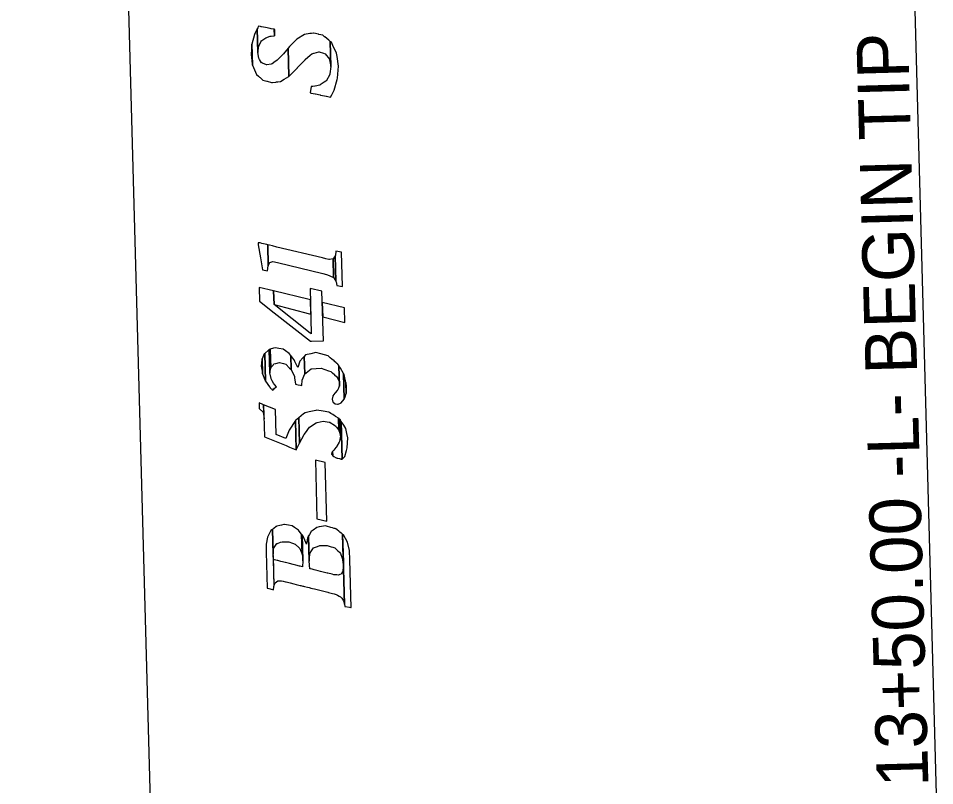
# Model space of a CAD drawing. Extents: x 1835096 to 1837089, y 993071 to 995976.
# Drawn here: x 1835140.8 to 1835495.4, y 994065.2 to 994362.2 of the extents above; entities that cross this region are included whole.
import ezdxf

# ---------------------------------------------------------------- set-up
doc = ezdxf.new("R2010")
doc.units = 0
for name, color, linetype in [('CTL Sheet Border CELL', 7, 'Continuous'), ('Default', 7, 'Continuous'), ('Sheet Data Field CELL', 7, 'Continuous')]:
    doc.layers.add(name, color=color, linetype=linetype)

msp = doc.modelspace()

# ---------------------------------------------------------------- linework, layer by layer
at = {"layer": 'CTL Sheet Border CELL'}
msp.add_lwpolyline([(1835140.76, 995926.46), (1835211.98, 993318.73), (1837037.37, 993368.58), (1836966.16, 995976.31)], close=True, dxfattribs=at)
at = {"layer": 'Default'}
msp.add_line((1835497.85, 993999.18), (1835481.16, 994610.43), dxfattribs=at)
at = {"layer": 'Sheet Data Field CELL'}
for points in [[(1835238.65, 994355.27), (1835239.88, 994355.41), (1835239.81, 994357.91), (1835238.57, 994358.15), (1835238.26, 994358.21), (1835238.2, 994358.22), (1835236.47, 994358.56), (1835236.47, 994358.55), (1835236.4, 994358.57), (1835234.85, 994358.86), (1835234.68, 994358.9), (1835234.68, 994358.9), (1835234.47, 994358.94), (1835233.75, 994359.08), (1835233.6, 994358.79), (1835233.47, 994358.54), (1835233.22, 994358.05), (1835233.47, 994348.99), (1835233.69, 994350.55), (1835233.8, 994351.37), (1835233.95, 994351.66), (1835234.63, 994353.01), (1835234.83, 994353.41), (1835235, 994353.53), (1835236.51, 994354.64), (1835236.58, 994354.67), (1835238.28, 994355.23), (1835238.34, 994355.23)], [(1835243.59, 994338.57), (1835245.48, 994339.66), (1835245.18, 994350.6), (1835243.32, 994348.46), (1835241.9, 994347), (1835241.9, 994346.99), (1835240.95, 994346.01), (1835240.39, 994345.59), (1835240.15, 994345.41), (1835238.95, 994344.5), (1835238.63, 994344.44), (1835238.58, 994344.43), (1835236.87, 994344.1), (1835236.79, 994344.13), (1835235.24, 994344.82), (1835235.07, 994344.9), (1835235.07, 994344.89), (1835234.85, 994344.99), (1835234.1, 994346.25), (1835233.94, 994346.52), (1835233.79, 994346.77), (1835233.47, 994348.99), (1835233.22, 994358.05), (1835232.46, 994356.57), (1835232.14, 994355.95), (1835231.12, 994352.15), (1835231.35, 994344.02), (1835232.54, 994341.28), (1835232.9, 994340.46), (1835233.72, 994339.73), (1835233.99, 994339.49), (1835234.13, 994339.36), (1835234.29, 994339.22), (1835235.03, 994338.57), (1835235.24, 994338.38), (1835235.42, 994338.23), (1835236.97, 994337.8), (1835237.04, 994337.78), (1835238.77, 994337.3), (1835238.83, 994337.29), (1835239.14, 994337.33), (1835240.37, 994337.5), (1835240.61, 994337.53), (1835241.18, 994337.61), (1835242.16, 994337.75)], [(1835239.88, 994355.41), (1835240.06, 994357.86), (1835239.81, 994357.91)], [(1835261.21, 994346.14), (1835261.74, 994343.51), (1835261.47, 994353.25), (1835261.01, 994353.64), (1835260.96, 994353.67), (1835260.95, 994353.68), (1835259.36, 994355), (1835259.3, 994355.05), (1835258.66, 994355.59), (1835257.05, 994355.96), (1835256.88, 994356.01), (1835255.07, 994356.44), (1835254.95, 994356.47), (1835254.16, 994356.33), (1835253.51, 994356.23), (1835251.52, 994355.89), (1835251.46, 994355.89), (1835248.54, 994354.09), (1835248.51, 994354.08), (1835245.7, 994351.2), (1835245.18, 994350.6), (1835245.48, 994339.66), (1835246, 994340.19), (1835248.81, 994343.04), (1835248.84, 994343.08), (1835251.72, 994346.11), (1835251.79, 994346.17), (1835253.74, 994347.89), (1835254.38, 994348.45), (1835255.17, 994348.67), (1835255.28, 994348.7), (1835257.07, 994349.22), (1835257.24, 994349.16), (1835258.84, 994348.67), (1835259.48, 994348.48), (1835259.54, 994348.46), (1835261.15, 994346.4), (1835261.16, 994346.39)], [(1835231.28, 994344.61), (1835231.35, 994344.02), (1835231.12, 994352.15), (1835231.08, 994351.98), (1835230.87, 994348.12)], [(1835264.34, 994338.99), (1835264.64, 994343.68), (1835264.11, 994347.4), (1835263.93, 994348.68), (1835262.48, 994351.69), (1835261.91, 994352.89), (1835261.47, 994353.25), (1835261.74, 994343.51), (1835261.36, 994340.7), (1835261.33, 994340.44), (1835261.32, 994340.38), (1835259.83, 994337.88), (1835259.77, 994337.8), (1835259.15, 994337.39), (1835257.59, 994336.36), (1835257.42, 994336.32), (1835255.63, 994335.88), (1835255.51, 994335.87), (1835254.73, 994335.82), (1835254.07, 994335.78), (1835253.68, 994333.29), (1835254.14, 994333.19), (1835254.8, 994333.06), (1835255.6, 994332.9), (1835255.71, 994332.88), (1835257.53, 994332.52), (1835257.69, 994332.48), (1835259.3, 994332.16), (1835259.93, 994332.03), (1835259.99, 994332.02), (1835261.55, 994331.71), (1835261.56, 994331.7), (1835261.61, 994331.7), (1835262.04, 994332.52), (1835262.45, 994333.32), (1835262.96, 994334.3), (1835264.2, 994338.52)], [(1835237.21, 994264.43), (1835237.5, 994266.44), (1835237.28, 994274.54), (1835236.93, 994274.63), (1835235.01, 994275.09), (1835234.32, 994275.26), (1835233.6, 994275.23), (1835233.61, 994274.54), (1835233.63, 994274.46), (1835234.48, 994269.51), (1835235.29, 994264.78)], [(1835261.37, 994262.55), (1835262.76, 994261.85), (1835262.56, 994269.07), (1835261.19, 994268.84), (1835260.92, 994268.88), (1835259.81, 994269.08), (1835258.42, 994269.42), (1835240.86, 994273.67), (1835239.11, 994274.1), (1835237.94, 994274.38), (1835237.28, 994274.54), (1835237.5, 994266.43), (1835238.12, 994267.73), (1835239.27, 994268.02), (1835241.02, 994267.73), (1835258.58, 994263.45), (1835259.97, 994263.03), (1835261.09, 994262.7)], [(1835264.03, 994258.77), (1835266.18, 994258.4), (1835265.82, 994271.62), (1835263.67, 994272.08), (1835263.45, 994270.37), (1835263.39, 994270.27), (1835263.66, 994260.46), (1835263.73, 994260.14)], [(1835262.85, 994261.69), (1835263.66, 994260.47), (1835263.39, 994270.27), (1835262.65, 994269.09), (1835262.56, 994269.07), (1835262.76, 994261.84)], [(1835254.21, 994237.23), (1835258.8, 994237.36), (1835258.27, 994256.56), (1835253.65, 994257.65), (1835254.14, 994240.05), (1835253.7, 994240.38), (1835239.71, 994251.36), (1835239.56, 994256.66), (1835233.93, 994258.01), (1835234.07, 994252.69), (1835239.79, 994248.2), (1835253.79, 994237.22)], [(1835253.5, 994247.87), (1835253.92, 994247.77), (1835253.77, 994253.27), (1835253.35, 994253.37), (1835239.56, 994256.66), (1835239.71, 994251.36)], [(1835258.54, 994246.63), (1835267.09, 994244.5), (1835266.93, 994250.13), (1835258.39, 994252.17)], [(1835236.21, 994222.26), (1835236.4, 994221.8), (1835236.11, 994232.49), (1835235.94, 994232.33), (1835235.1, 994230.35), (1835235.26, 994224.58)], [(1835239.96, 994219), (1835240.63, 994219.55), (1835239.92, 994220.46), (1835239.54, 994220.95), (1835238.99, 994221.94), (1835238.59, 994222.67), (1835238.55, 994222.75), (1835238.12, 994224.93), (1835237.87, 994234.04), (1835237.81, 994234.02), (1835237.55, 994233.79), (1835236.11, 994232.49), (1835236.4, 994221.79), (1835237.94, 994219.6), (1835238.21, 994219.29), (1835238.28, 994219.22), (1835238.66, 994218.79), (1835238.7, 994218.74), (1835239.09, 994218.31), (1835239.6, 994218.71)], [(1835238.44, 994226.74), (1835238.48, 994226.96), (1835238.28, 994234.14), (1835238.24, 994234.14), (1835237.87, 994234.04), (1835238.12, 994224.93)], [(1835245.72, 994226.84), (1835246.33, 994226.24), (1835246.18, 994231.72), (1835245.57, 994232.51), (1835244.14, 994233.47), (1835243.22, 994234.1), (1835241.63, 994234.41), (1835240.28, 994234.67), (1835240.22, 994234.65), (1835239.54, 994234.48), (1835239.54, 994234.47), (1835239.17, 994234.38), (1835238.66, 994234.24), (1835238.28, 994234.15), (1835238.48, 994226.95), (1835238.84, 994227.39), (1835239.34, 994227.99), (1835239.7, 994228.41), (1835240.38, 994228.6), (1835240.44, 994228.62), (1835241.77, 994228.99), (1835243.37, 994228.54), (1835244.28, 994228.29)], [(1835250.62, 994222.19), (1835251.58, 994224.64), (1835251.4, 994231.35), (1835250.4, 994230.24), (1835250.2, 994230.03), (1835249.68, 994229.46), (1835248.91, 994227.01), (1835247.79, 994229.37), (1835247.48, 994230.04), (1835247.43, 994230.11), (1835246.18, 994231.72), (1835246.33, 994226.24), (1835247.61, 994223.56), (1835247.67, 994223.11), (1835248.03, 994220.58), (1835249.09, 994220.37), (1835249.93, 994220.21), (1835250.47, 994220.1)], [(1835264.9, 994221.7), (1835264.99, 994219.85), (1835264.77, 994227.74), (1835264.73, 994227.82), (1835264.38, 994228.4), (1835264.11, 994228.63), (1835264.07, 994228.65), (1835263.79, 994228.89), (1835263.02, 994229.54), (1835262.94, 994229.6), (1835262.13, 994230.28), (1835262.08, 994230.33), (1835261.5, 994230.81), (1835260.66, 994231.52), (1835257.83, 994232.29), (1835255.88, 994232.82), (1835253.92, 994232.39), (1835251.94, 994231.95), (1835251.4, 994231.35), (1835251.58, 994224.63), (1835252.13, 994225.04), (1835254.08, 994226.48), (1835256.05, 994226.61), (1835257.98, 994226.74), (1835260.82, 994225.79), (1835261.65, 994225.52), (1835262.22, 994225.04), (1835262.28, 994225), (1835263.08, 994224.32), (1835263.16, 994224.25), (1835263.94, 994223.6), (1835264.23, 994223.03), (1835264.26, 994222.96), (1835264.54, 994222.41)], [(1835235.09, 994225.65), (1835235.26, 994224.58), (1835235.1, 994230.35), (1835234.97, 994230.02), (1835234.78, 994227.5)], [(1835265.75, 994213.33), (1835266.9, 994214.78), (1835266.63, 994224.68), (1835265.38, 994226.74), (1835264.77, 994227.74), (1835264.99, 994219.85), (1835264.95, 994219.76), (1835264.63, 994219.03), (1835264.38, 994218.47), (1835264.35, 994218.43), (1835264.09, 994218.11), (1835263.35, 994217.24), (1835263.28, 994217.14), (1835262.52, 994216.14), (1835262.47, 994215.95), (1835262.18, 994214.82), (1835262.18, 994214.82), (1835262.53, 994213.68), (1835262.59, 994213.64), (1835263.39, 994212.98), (1835263.47, 994212.97), (1835264.23, 994212.88), (1835264.51, 994212.84), (1835264.54, 994212.86), (1835264.8, 994212.96), (1835265.13, 994213.09), (1835265.17, 994213.11)], [(1835267.06, 994215.29), (1835267.62, 994217), (1835267.5, 994221.21), (1835266.82, 994224.38), (1835266.63, 994224.68), (1835266.9, 994214.78)], [(1835267.62, 994216.99), (1835267.72, 994220.22), (1835267.5, 994221.21)], [(1835235.5, 994209.79), (1835235.84, 994207.17), (1835235.69, 994212.62), (1835235.42, 994212.73), (1835233.96, 994213.32), (1835234.01, 994211.24)], [(1835248.27, 994195.23), (1835248.28, 994195.23), (1835247.97, 994206.55), (1835247.96, 994206.55), (1835245.56, 994202.77), (1835244.29, 994199.53), (1835240.52, 994201.11), (1835240.26, 994210.8), (1835235.69, 994212.62), (1835236.03, 994200.22), (1835240.6, 994198.36), (1835244.36, 994196.83), (1835245.74, 994196.27)], [(1835263.86, 994203.97), (1835264.8, 994202.74), (1835264.67, 994207.39), (1835263.75, 994207.99), (1835263.52, 994208.14), (1835263.33, 994208.25), (1835262.43, 994208.83), (1835262, 994209.11), (1835261.72, 994209.29), (1835261.2, 994209.63), (1835260.97, 994209.77), (1835258.67, 994210.15), (1835256.33, 994210.54), (1835255.87, 994210.43), (1835253.25, 994209.85), (1835251.71, 994209.51), (1835251.18, 994209.09), (1835249.33, 994207.62), (1835249.6, 994197.76), (1835251.4, 994201.11), (1835251.92, 994201.82), (1835253.41, 994203.9), (1835256, 994205.69), (1835256.46, 994205.78), (1835258.78, 994206.24), (1835261.08, 994205.88), (1835261.3, 994205.85), (1835261.83, 994205.52), (1835262.11, 994205.35), (1835262.53, 994205.08), (1835263.44, 994204.53), (1835263.62, 994204.28)], [(1835248.28, 994195.23), (1835249.6, 994197.77), (1835249.33, 994207.62), (1835247.97, 994206.55)], [(1835265.66, 994191.64), (1835266.13, 994191.52), (1835265.73, 994206.17), (1835265.25, 994206.91), (1835265.42, 994200.65), (1835265.31, 994199.89), (1835265.11, 994198.44), (1835264.93, 994198.11), (1835264.06, 994196.55), (1835263.84, 994196.28), (1835263.84, 994196.27), (1835263.67, 994196.07), (1835262.81, 994195.04), (1835262.4, 994194.51), (1835262.45, 994192.87), (1835262.87, 994192.64), (1835263.77, 994192.15), (1835263.96, 994192.04), (1835264.19, 994191.99), (1835265.1, 994191.78), (1835265.29, 994191.73), (1835265.54, 994191.67)], [(1835265.28, 994201.12), (1835265.42, 994200.65), (1835265.25, 994206.91), (1835265.11, 994207.11), (1835264.87, 994207.27), (1835264.67, 994207.39), (1835264.8, 994202.73), (1835265.01, 994202.03)], [(1835268.08, 994196.02), (1835268.29, 994199.87), (1835267.92, 994201.57), (1835267.52, 994203.45), (1835266.72, 994204.67), (1835265.73, 994206.17), (1835266.13, 994191.53), (1835267.05, 994192.66), (1835267.76, 994194.97)], [(1835262.16, 994193.25), (1835262.45, 994192.88), (1835262.4, 994194.51), (1835262.14, 994194.17), (1835261.99, 994193.48), (1835261.99, 994193.47)], [(1835256.33, 994168.46), (1835260.11, 994167.56), (1835259.49, 994190.31), (1835255.71, 994191.21)], [(1835239.69, 994142.38), (1835239.75, 994142.54), (1835239.47, 994152.76), (1835239.36, 994154.35), (1835239.33, 994154.88), (1835239.07, 994164.39), (1835238.91, 994164.28), (1835238.47, 994163.95), (1835237.15, 994161.42), (1835236.7, 994158.69), (1835236.73, 994155.55), (1835237.1, 994141.68), (1835237.17, 994141.66), (1835237.69, 994141.53), (1835239.09, 994141.16), (1835239.55, 994141.05), (1835239.67, 994142.22)], [(1835249.65, 994157.02), (1835250.58, 994154.8), (1835250.37, 994162.57), (1835249.47, 994163.71), (1835249.21, 994164.05), (1835247.69, 994165.09), (1835246.72, 994165.76), (1835245.32, 994166.03), (1835243.74, 994166.33), (1835243.57, 994166.29), (1835242.66, 994166.09), (1835241.99, 994165.94), (1835240.85, 994165.7), (1835240.61, 994165.52), (1835240.6, 994165.51), (1835239.62, 994164.79), (1835239.36, 994164.61), (1835239.36, 994164.6), (1835239.15, 994164.45), (1835239.09, 994164.41), (1835239.09, 994164.4), (1835239.07, 994164.39), (1835239.33, 994154.87), (1835239.34, 994155.03), (1835239.39, 994155.5), (1835239.56, 994157.07), (1835239.82, 994157.44), (1835240.78, 994158.89), (1835240.79, 994158.89), (1835241.03, 994158.98), (1835242.17, 994159.4), (1835242.83, 994159.65), (1835243.75, 994159.62), (1835243.92, 994159.62), (1835245.49, 994159.59), (1835246.9, 994159.06), (1835247.87, 994158.69), (1835249.39, 994157.26)], [(1835266.25, 994152.51), (1835266.55, 994151.55), (1835266.25, 994162.55), (1835265.97, 994162.77), (1835265.75, 994162.94), (1835265.75, 994162.94), (1835265.2, 994163.37), (1835265.19, 994163.38), (1835264.78, 994163.7), (1835264.18, 994164.17), (1835263.59, 994164.64), (1835263.37, 994164.7), (1835263.02, 994164.8), (1835262.32, 994165), (1835261.67, 994165.18), (1835260.04, 994165.65), (1835259.78, 994165.73), (1835257.24, 994165.34), (1835256.31, 994165.2), (1835254.81, 994164.12), (1835254.03, 994163.56), (1835253.43, 994162.47), (1835253.2, 994162.04), (1835253.1, 994161.86), (1835253.36, 994152.14), (1835253.44, 994153.03), (1835253.63, 994155.1), (1835254.24, 994156.05), (1835254.99, 994157.23), (1835256.51, 994157.79), (1835257.44, 994158.15), (1835259.99, 994158.17), (1835260.24, 994158.18), (1835261.88, 994157.69), (1835262.53, 994157.49), (1835263.23, 994157.28), (1835263.59, 994156.93), (1835263.8, 994156.72), (1835264.4, 994156.13), (1835265.01, 994155.54), (1835265.42, 994155.14), (1835265.43, 994155.13), (1835266.02, 994153.25)], [(1835266.98, 994135.59), (1835267.01, 994135.53), (1835266.27, 994162.54), (1835266.25, 994162.55), (1835266.55, 994151.55), (1835266.36, 994148.26), (1835266.16, 994147.94), (1835265.65, 994147.13), (1835265.65, 994147.12), (1835265.64, 994147.11), (1835265.24, 994146.94), (1835264.66, 994146.7), (1835264.07, 994146.76), (1835264.07, 994146.76), (1835263.86, 994146.78), (1835263.86, 994146.78), (1835263.51, 994146.81), (1835262.82, 994146.88), (1835262.17, 994147.04), (1835260.53, 994147.45), (1835260.28, 994147.51), (1835257.71, 994148.15), (1835256.77, 994148.39), (1835255.23, 994148.77), (1835254.43, 994148.96), (1835254.43, 994148.96), (1835253.79, 994149.12), (1835253.55, 994149.18), (1835253.36, 994152.14), (1835253.1, 994161.86), (1835252.72, 994161.19), (1835252.22, 994158.68), (1835251.04, 994161.72), (1835250.58, 994162.31), (1835250.85, 994152.19), (1835250.79, 994149.91), (1835250.71, 994149.93), (1835250.71, 994149.92), (1835249.84, 994150.15), (1835249.59, 994150.21), (1835248.09, 994150.59), (1835248.09, 994150.58), (1835247.12, 994150.83), (1835245.72, 994151.18), (1835244.14, 994151.58), (1835243.97, 994151.63), (1835243.05, 994151.86), (1835242.37, 994152.03), (1835241.21, 994152.32), (1835240.97, 994152.38), (1835240.96, 994152.39), (1835239.95, 994152.64), (1835239.68, 994152.71), (1835239.47, 994152.76), (1835239.36, 994154.35), (1835239.69, 994142.38), (1835239.75, 994142.54), (1835239.94, 994143.08), (1835240.19, 994143.75), (1835241.17, 994144.45), (1835241.18, 994144.46), (1835241.43, 994144.46), (1835242.57, 994144.45), (1835243.25, 994144.32), (1835244.18, 994144.14), (1835244.35, 994144.1), (1835245.93, 994143.7), (1835247.33, 994143.36), (1835248.29, 994143.12), (1835249.79, 994142.75), (1835250.05, 994142.69), (1835250.92, 994142.47), (1835250.99, 994142.45), (1835251.12, 994142.42), (1835251.57, 994142.31), (1835252.68, 994142.03), (1835253.25, 994141.89), (1835253.64, 994141.79), (1835253.75, 994141.77), (1835254, 994141.71), (1835254.63, 994141.55), (1835255.43, 994141.35), (1835256.97, 994140.97), (1835257.91, 994140.74), (1835260.48, 994140.1), (1835260.74, 994140.04), (1835262.37, 994139.64), (1835263.02, 994139.44), (1835263.72, 994139.21), (1835264.07, 994139.11), (1835264.29, 994138.97), (1835264.88, 994138.63), (1835265.48, 994138.28), (1835265.89, 994137.74), (1835265.9, 994137.73), (1835266.46, 994137.01), (1835266.69, 994136.39)], [(1835250.68, 994153.83), (1835250.85, 994152.19), (1835250.58, 994162.31), (1835250.44, 994162.48), (1835250.44, 994162.47), (1835250.37, 994162.57), (1835250.58, 994154.79)], [(1835269.48, 994134.17), (1835269.58, 994134.14), (1835269.07, 994152.65), (1835268.88, 994156.19), (1835268.18, 994159.5), (1835266.54, 994162.33), (1835266.38, 994162.45), (1835266.27, 994162.54), (1835267.01, 994135.53), (1835267.14, 994134.62), (1835267.3, 994134.6), (1835268.86, 994134.29)]]:
    msp.add_lwpolyline(points, close=True, dxfattribs=at)

# ---------------------------------------------------------------- texts
at = {"layer": 'Default'}
msp.add_text('STA. 13+50.00 -L- BEGIN TIP PROJECT B-5341', height=20, rotation=91.5643, dxfattribs=at).set_placement((1835494.81, 993998.08))

doc.saveas('drawing.dxf')
